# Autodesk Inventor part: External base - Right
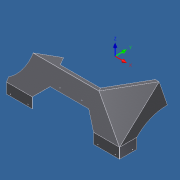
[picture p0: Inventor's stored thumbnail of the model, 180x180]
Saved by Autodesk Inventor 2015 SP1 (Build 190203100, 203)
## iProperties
Category: Mechanical Engineering Drawing and Design - CADD
Manager: Fábio Ricardo de Oliveira Souza
Company: SENAI - Serviço Nacional de Aprendizagem Industrial
Created: 2011-06
Part Number: External base - Right
Material: Steel
Description: Stainless Steel (DIN- X6CrNiTi18-10)
Document SubType Name: Sheet Metal
Designer: Guilherme Augusto Franco de Souza
Engineer: George Geraldo de Oliveia Silva
Authority: Fábio Ricardo de Oliveira Soza
Density: 7.85 g/cm^3
Sheet Metal Rule: Default_mm
Sheet Metal Width: 403,081 mm
Sheet Metal Length: 744,042 mm
Sheet Metal Area: 299909,128 mm^2
Flat Pattern Width: 40.3081 cm
Flat Pattern Length: 74.4042 cm
Flat Pattern Area: 2999.09 cm^2
Appearance: Machined 02
Subject: WorldSkill 2011 - London, England
Author: Guilherme Augusto Franco de Souza
Revision Number: 00
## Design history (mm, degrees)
sketch "Sketch1"
  geometry: L1 (-253, 219.104)-(-253, -219.104); L2 (-253, -219.104)-(126.5, -219.104); L3 (126.5, -219.104)-(253, 0); L4 (253, 0)-(126.5, 219.104); L5 (-253, 219.104)-(126.5, 219.104); L6 (-230.94, 0)-(-115.47, 200); L7 (-115.47, 200)-(115.47, 200); L8 (115.47, 200)-(230.94, 0); L9 (230.94, 0)-(115.47, -200); L10 (115.47, -200)-(-115.47, -200); L11 (-115.47, -200)-(-230.94, 0); A1 r 253 centre (0, 0) between (126.5, -219.104) and (253, 0); 2 further points
  constraints: 22 end point, 3 point on circle, 2 coincident, 2 horizontal alignment, 2 parallel, 1 centre point, 1 equal length, 1 perpendicular, 1 tangent, 1 vertical, 13 other
  dimensions: "d0" = 506 diameter of A1; "d1" = 200 distance from line of point (0, 0) L10
patch "Boundary Patch1" sketch "Sketch1"
sketch "Sketch2"
  geometry: L1 (-219.104, 0)-(-300, -140.115); L2 (-300, -140.115)-(-300, -200); 2 further points
  constraints: 4 end point, 1 vertical
  dimensions: "d3" = 30 deg angle of L2 L1; "d4" = 300 distance from line of point (0, 0) L2; "d26" = 200 vertical distance of point (0, 0) L2.end
extrude_surface "ExtrusionSrf1" sketch "Sketch2" dims "d5" = 650, "d6" = 0
mirror "Mirror1"
sketch "Sketch3"
  geometry: L1 (325, -140.115)-(325, -200) reference; L2 (325, -120)-(325, -140.115); A1 r 136 centre (389, 0) between (253, 0) and (325, -120); 1 further point
  constraints: 2 end point, 2 point on circle, 1 centre point, 1 collinear, 1 horizontal alignment, 1 vertical alignment
  dimensions: "d7" = 120 vertical distance of A1.start L2.start
extrude_surface "ExtrusionSrf3" sketch "Sketch3" dims "d8" = 600, "d9" = 0
feature "Trim1"
feature "Trim2"
feature "Trim3"
feature "Trim4"
sketch "Sketch4"
  geometry: L1 (-325, -200)-(-325, -140.115) reference; L2 (-325, -140.115)-(-253, 0); 1 further point
  constraints: 2 end point
extrude_surface "ExtrusionSrf4" sketch "Sketch4" dims "d10" = 600, "d11" = 0
workplane "Work Plane1"
feature "Trim5"
feature "Trim6"
workplane "Work Plane2"
feature "Trim7"
feature "Trim8"
patch "Boundary Patch2" dims "d12" = 0, "d13" = 0, "d14" = 0, "d15" = 0
patch "Boundary Patch3" dims "d16" = 0, "d17" = 0, "d18" = 0, "d19" = 0
sketch "Sketch5"
  geometry: L1 (-200, -200)-(-200, -140); L2 (200, -200)-(200, -140); L3 (-300, -200)-(300, -200) reference; A1 r 440.667 centre (0, -532.667) between (200, -140) and (-200, -140); 1 further point
  constraints: 4 end point, 2 parallel, 2 point on circle, 1 centre point, 1 horizontal alignment, 1 point on line, 1 vertical, 1 vertical alignment
  dimensions: "d21" = 60 distance of L1.start L1.end; "d22" = 400 distance between parallel lines of L2 L1; "d23" = 108 distance edge to line of A1 L3
extrude_surface "ExtrusionSrf5" sketch "Sketch5" dims "d24" = 600, "d25" = 0
feature "Trim9"
feature "Stitch Surface1"
sketch "Sketch16"
  geometry: L1 (176, -200)-(176, -140); L2 (176, -140)-(111, -75); L3 (111, -75)-(-111, -75); L4 (-111, -75)-(-176, -140); L5 (-176, -140)-(-176, -200); L6 (325, -200)-(-325, -200) reference; 1 further point
  constraints: 10 end point, 2 equal length, 1 horizontal alignment, 1 parallel, 1 perpendicular, 1 point on line, 1 vertical
  dimensions: "d68" = 352 distance between parallel lines of L5 L1; "d69" = 176 distance from line of point (0, 0) L1 (= 0.5 x d68); "d70" = 125 distance between parallel lines of L6 L3; "d71" = 60 distance of L4.end L5.end; "d72" = 222 distance of L2.end L3.end
extrude_surface "ExtrusionSrf6" sketch "Sketch16" dims "d73" = 600, "d74" = 0
feature "Trim10"
feature "Trim11"
sketch "Sketch19"
  geometry: L1 (126.5, -218.854)-(-232.948, -218.854); L2 (-232.948, -218.854)-(-232.948, -219.354); L3 (-232.948, -219.354)-(126.5, -219.354); L4 (126.5, -219.354)-(126.5, -218.854); 2 further points
  constraints: 8 end point, 2 parallel, 1 coincident, 1 horizontal, 1 midpoint, 1 perpendicular
  dimensions: "d102" = 0.5 distance of L3.end L1.start
extrude_surface "ExtrusionSrf7" sketch "Sketch19" dims "d103" = 200, "d104" = 0
feature "Trim12"
sketch "Sketch20"
  geometry: L1 (357.44, 219.104)-(241.97, 419.104) reference; L2 (379.5, 438.209)-(268.08, 373.881); 1 further point
  constraints: 2 end point, 1 perpendicular, 1 point on line
extrude_surface "ExtrusionSrf8" sketch "Sketch20" dims "d105" = 10, "d106" = 0
sketch "Sketch21"
  geometry: L1 (241.97, 19.104)-(357.44, 219.104) reference; L2 (379.5, 0)-(268.08, 64.328); 1 further point
  constraints: 2 end point, 1 perpendicular, 1 point on line
extrude_surface "ExtrusionSrf9" sketch "Sketch21" dims "d107" = 10, "d108" = 0
split "Split2"
split "Split3"
fillet "Fillet2" dims "d113" = 1.25
fillet "Fillet3" dims "d114" = 1.25
delete_face "Delete Face3"
delete_face "Delete Face4"
delete_face "Delete Face5"
delete_face "Delete Face6"
delete_face "Delete Face7"
feature "Trim13"
delete_face "Delete Face8"
thicken "Thicken2" dims "d115" = 1
feature "Rip14" dims "d116" = 1 (= GapSize)
feature "Rip15" dims "d117" = 0.5 (= 0.5 x GapSize)
node "Unfold1"
delete_face "Delete Face9"
sketch "Sketch24"
  geometry: L1 (438.019, -69.739)-(437.721, -69.602) reference; L2 (418.516, 262.221)-(418.381, 261.929) reference; L3 (435.347, -69.117)-(434.91, -69.14) reference; L4 (434.91, -69.14)-(417.944, 261.907) reference; L5 (432.329, -72.17)-(431.956, -72.628) reference; L6 (431.956, -72.628)-(237.483, 85.881) reference; L7 (431.248, -74.854)-(431.248, -75.215) reference; L8 (434.75, -134.765)-(434.75, -74.017) reference; L9 (435.129, -69.129)-(435.432, -75.034); L10 (431.248, -75.034)-(435.432, -75.034); L11 (437.87, -69.67)-(434.046, -77.958); L12 (432.143, -72.399)-(437.721, -76.946); C1 r 1.5 at (434.75, -74.017); 1 further point
  constraints: 8 end point, 4 midpoint, 3 parallel, 1 centre point, 1 coincident, 1 perpendicular
  dimensions: "d119" = 3 diameter of C1
cut "Cut10" sketch "Sketch24" dims "d120" = 1 (= Thickness), "d121" = 0
sketch "Sketch25"
  geometry: L1 (417.944, 261.907)-(237.856, 86.338) reference; L2 (237.483, 85.881)-(-140.756, 85.881) reference; L3 (-140.75, 86.603)-(237.192, 86.603) reference; L4 (237.78, 86.826)-(417.663, 262.195) reference; L5 (236.014, 86.242)-(237.469, 86.242); L6 (238.561, 87.306)-(237.469, 86.242); L7 (237.856, 86.338)-(432.329, -72.17) reference; L8 (431.956, -72.628)-(237.483, 85.881) reference; L9 (232.162, 107.506)-(237.78, 86.826) reference; L10 (237.192, 86.603)-(226.179, 104.986) reference; L11 (237.192, 86.603)-(238.343, 84.682); L12 (238.176, 85.697)-(237.487, 86.259); C1 r 1.5 at (237.487, 86.259); 1 further point
  constraints: 8 end point, 3 parallel, 1 centre point, 1 coincident, 1 collinear, 1 point on line
  dimensions: "d122" = 0.72257 distance between parallel lines of L3 L2 (derived); "d123" = 0.36128 distance between parallel lines of L3 L5 (= 0.5 x d122); "d124" = 0.40244 distance between parallel lines of L4 L1 (derived); "d127" = 0.20122 distance between parallel lines of L1 L6 (= 0.5 x d124); "d131" = 3 diameter of C1; "d132" = 0.59032 distance between parallel lines of L7 L8 (derived); "d133" = 0.29516 distance between parallel lines of L7 L12 (= 0.5 x d132)
cut "Cut11" sketch "Sketch25" dims "d129" = 1 (= Thickness), "d130" = 0
sketch "Sketch26"
  geometry: L1 (418.381, 261.929)-(435.347, -69.117) reference; L2 (434.91, -69.14)-(417.944, 261.907) reference; L3 (417.944, 261.907)-(238.691, 87.153) reference; L4 (238.411, 87.441)-(417.663, 262.195) reference; L5 (417.331, 261.59)-(418.139, 262.378); L6 (418.2, 261.193)-(418.139, 262.378); C1 r 1.5 at (418.139, 262.378); 1 further point
  constraints: 4 end point, 2 parallel, 1 centre point, 1 coincident
  dimensions: "d134" = 0.40244 distance between parallel lines of L4 L3 (derived); "d135" = 0.20122 distance between parallel lines of L4 L5 (= 0.5 x d134); "d136" = 0.43741 distance between parallel lines of L1 L2 (derived); "d137" = 0.2187 distance between parallel lines of L1 L6 (= 0.5 x d136); "d138" = 3 diameter of C1
cut "Cut12" sketch "Sketch26" dims "d139" = 1 (= Thickness), "d140" = 0
node "Refold1"
node "Refold2"
sketch "Sketch27"
  geometry: L1 (0, 55.55)-(0, 0) reference; L2 (149, 55.258)-(149, -4) reference; L3 (24.5, 7)-(124.5, 7); L4 (-499.75, -4)-(-352, -4) reference; L5 (-352, -4)-(-352, 55.55) reference; 6 further points; 1 other entity
  constraints: 2 end point, 2 horizontal alignment, 1 midpoint, 1 other
  dimensions: "d147" = 11 dimension on L3.end; "d148" = 100 distance of L3.start L3.end; "d149" = 24.5 distance from line of L1 L3.start; "d150" = 11 distance from line of L4 point (-376.5, 7); "d151" = 100 distance of point (-476.5, 7) point (-376.5, 7); "d152" = 24.5 distance from line of point (-376.5, 7) L5
hole "Hole4" sketch "Sketch27" at (124.5, 7), (24.5, 7), (-376.5, 7), (-476.5, 7) diameter "d153" = 3.3; stored, may be unused: countersink angle "d157" = 90 deg, drill point angle "d159" = 118 deg; dims "d154" = 6, "d155" = 4, "d156" = 2, "d158" = 1 (derived)
sketch "Sketch28"
  geometry: L1 (55.582, 0)-(0, 0) reference; 4 further points; 1 other entity
  constraints: 1 other
  dimensions: "d160" = 11 dimension on point (7, -25); "d161" = 25 distance from line of L1 point (7, -25)
hole "Hole5" sketch "Sketch28" at (7, -25) diameter "d162" = 3.3; stored, may be unused: countersink angle "d166" = 90 deg, drill point angle "d168" = 118 deg; dims "d163" = 6, "d164" = 4, "d165" = 2, "d167" = 1 (derived)
node "Hole1"
body "Solid2"
body "Srf1"
body "Srf2"
body "Srf3"
body "Srf4"
body "Srf5"
body "Srf6"
body "Srf7"
body "Srf8"
body "Srf9"
body "Srf10"
body "Srf11"
body "Srf12"
body "Srf13"
sketch "Sketch29"
  geometry: 2 further points
hole "Hole6" sketch "Sketch29" diameter "d169" = 3.4; stored, may be unused: countersink angle "d173" = 90 deg, drill point angle "d175" = 0 deg; dims "d170" = 6, "d171" = 4, "d172" = 2, "d174" = 8
extrude_surface "ExtrusionSrf2"
feature "Definition1"
other parameters: "Thickness" = 1 (derived), "BendRadius" = 1 (= Thickness), "BendReliefWidth" = 1 (= Thickness), "BendReliefDepth" = 0.5 (= 0.5 x Thickness), "CornerReliefSize" = 4 (= 4 x Thickness), "SeamGap" = 0.01, "MinimumRemnant" = 2 (= 2 x Thickness), "TransitionRadius" = 1 (= BendRadius), "JacobiRadiusSize" = 1 (= BendRadius), "GapSize" = 1 (= Thickness), "d141" = 0, "d142" = 0, "d143" = 0, "d144" = 0, "d145" = 0, "d146" = 0, "BendRadius" = 1, "BendReliefDepth" = 0.5, "BendReliefWidth" = 1, "CornerReliefSize" = 4, "GapSize" = 1, "JacobiRadiusSize" = 1, "MinimumRemnant" = 2, "Thickness" = 1, "TransitionRadius" = 1
